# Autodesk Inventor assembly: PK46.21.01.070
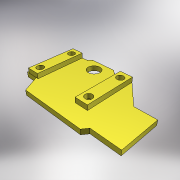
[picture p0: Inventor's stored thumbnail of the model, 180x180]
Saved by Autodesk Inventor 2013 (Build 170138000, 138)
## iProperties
Created: 2005-04
Part Number: PK46.21.01.070
Document SubType Name: Assembly
Designer: salex
Manufacturer: Standard
Standards Organization: Custom
Author: salex
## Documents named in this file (3)
- C:\Product Design Suite 2013 Test Drive\Dynamic Simulation\Workspace\Assy, Chassis, Front\PK46.21.01.070.iam
- C:\Product Design Suite 2013 Test Drive\Dynamic Simulation\Workspace\Assy, Chassis, Front\PK46.21.01.017.ipt
- C:\Product Design Suite 2013 Test Drive\Dynamic Simulation\Workspace\Assy, Chassis, Front\PK46.21.01.018.ipt
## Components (3 placed, 2 different names)
1. PK46.21.01.017:1 — Вставка:1, Вставка:2, Совмещение:1, Совмещение:2
2. PK46.21.01.018:1 — Вставка:1, Совмещение:1
3. PK46.21.01.018:2 — Вставка:2, Совмещение:2
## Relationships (4: Insert 2, Mate 2)
- Вставка:1 [Insert]: PK46.21.01.017:1 ↔ PK46.21.01.018:1
- Вставка:2 [Insert]: PK46.21.01.017:1 ↔ PK46.21.01.018:2
- Совмещение:1 [Mate]: PK46.21.01.017:1 ↔ PK46.21.01.018:1
- Совмещение:2 [Mate]: PK46.21.01.017:1 ↔ PK46.21.01.018:2
